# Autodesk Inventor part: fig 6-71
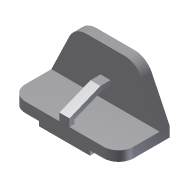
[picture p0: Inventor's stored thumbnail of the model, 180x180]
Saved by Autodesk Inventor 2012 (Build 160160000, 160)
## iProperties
Shininess: 77.0
Length Units: 11269
Angle Units: 11279
Time Units: 11290
Mass Units: 11283
Length Display Precision: 3
Angle Display Precision: 2
Created: 2001-12
Part Number: fig 6-71
Document SubType Name: Modeling
Designer: Renu Muthoo
Density: 1 g/cm^3
Material: Default
Density: 0.0
Volumn: 0.0
Area: 0.0
PropertySet Name: Model Information
Control State: 0
Master: False
Checked Out: False
Author: Renu Muthoo
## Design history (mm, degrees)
sketch "Sketch2"
  geometry: L1 (-67.219, 19.116)-(148.781, 19.116); L2 (148.781, 19.116)-(148.781, -0.884); L3 (-67.219, -0.884)-(-67.219, 19.116); L4 (-10.219, -0.884)-(-10.219, -9.884); L5 (-10.219, -9.884)-(91.781, -9.884); L6 (91.781, -9.884)-(91.781, -0.884); L7 (148.781, -0.884)-(91.781, -0.884); L8 (-10.219, -0.884)-(-67.219, -0.884)
  constraints: 16 end point, 5 parallel, 4 perpendicular, 2 equal length, 1 horizontal
  dimensions: "d0" = 102 distance of L4.end L5.end; "d1" = 57 distance of L4.start L3.start; "d2" = 29 distance between parallel lines of L1 L5; "d3" = 20 distance of L1.end L2.end
extrude "Extrusion1" new body sketch "Sketch2" distance "d4" = 102; taper "d5" = 0 deg
sketch "Sketch3"
  geometry: L1 (67.219, -19.116)-(-148.781, -19.116) reference; L2 (67.219, -19.116)-(31.475, -93.564); L3 (-2.781, -115.116)-(-78.781, -115.116); L4 (-113.038, -93.564)-(-148.781, -19.116); A1 r 38 centre (-2.781, -77.116) between (-2.781, -115.116) and (31.475, -93.564); A2 r 38 centre (-78.781, -77.116) between (-113.038, -93.564) and (-78.781, -115.116)
  constraints: 6 end point, 4 point on circle, 4 tangent, 2 centre point, 1 equal length, 1 equal radius, 1 parallel
  dimensions: "d6" = 96 distance between parallel lines of L3 L1; "d7" = 38 radius of A1; "d8" = 76 distance of A2.centre A1.centre
extrude "Extrusion2" join sketch "Sketch3" distance "d9" = 20; taper "d10" = 0 deg
fillet "Fillet1" dims "d11" = 30
workplane "Work Plane1"
sketch "Sketch7"
  geometry: L1 (0, -82)-(-15, -82); L2 (-15, -82)-(-40, -20); L3 (-40, -20)-(-40, 0); L4 (0, -82)-(20, -82) reference; L5 (0, 0)-(-74.447, 0) reference
  constraints: 6 end point, 2 point on line, 1 horizontal, 1 perpendicular
  dimensions: "d32" = 20 distance of L2.end L3.end; "d33" = 15 distance of L1.start L1.end; "d34" = 40 distance of L5.start L3.end
feature "Rib4" sketch "Sketch7" dims "d55" = 10, "d56" = 20, "d57" = 0
body "Solid1"
other parameters: "d12" = -108
